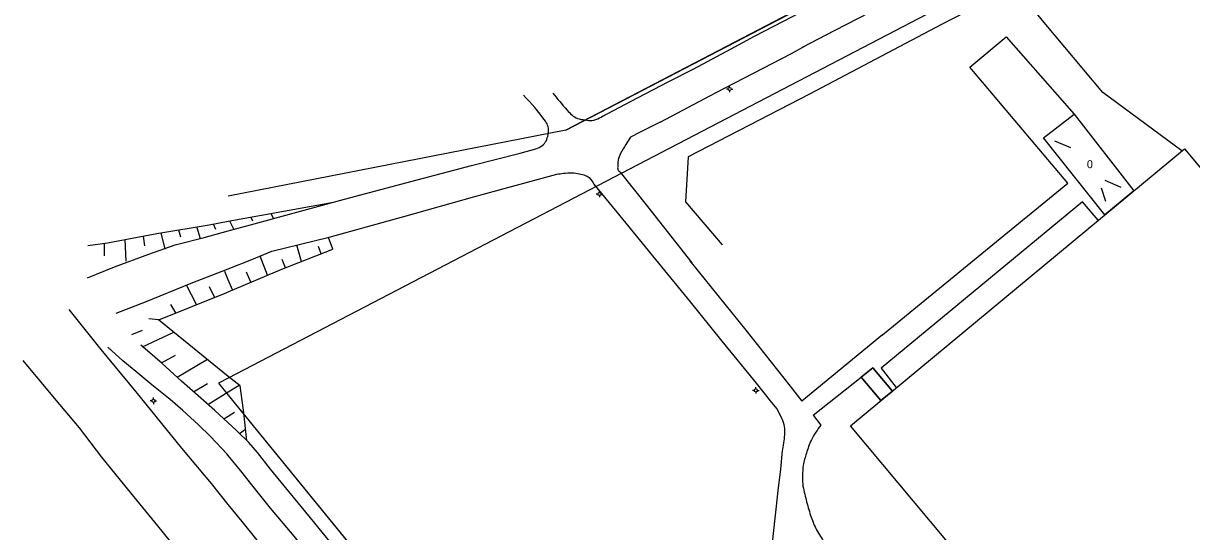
# Model space of a CAD drawing. Extents: x 1517229 to 1518128, y 6494851 to 6495271.
# Drawn here: x 1517631.6 to 1517777.6, y 6495029.8 to 6495093.3 of the extents above; entities that cross this region are included whole.
import ezdxf

# ---------------------------------------------------------------- set-up
doc = ezdxf.new("R2010")
doc.units = 0
doc.layers.add('Karta', color=7, linetype='Continuous')

msp = doc.modelspace()

# ---------------------------------------------------------------- linework, layer by layer
at = {"layer": 'Karta'}
for p, q in [((1517699.41, 6495080), (1517754.51, 6495108.72)), ((1517758.98, 6495102.02), (1517657.21, 6495048.98)), ((1517758.98, 6495102.02), (1517657.21, 6495048.98)), ((1517719.68, 6495085.13), (1517719.48, 6495085.13)), ((1517719.88, 6495085.33), (1517719.88, 6495085.53)), ((1517719.88, 6495084.93), (1517719.88, 6495084.73)), ((1517720.08, 6495085.13), (1517720.28, 6495085.13)), ((1517776.41, 6495077.41), (1517766.55, 6495084.69)), ((1517699.41, 6495080), (1517657.21, 6495071.73)), ((1517699.41, 6495080), (1517657.21, 6495071.73)), ((1517760.5, 6495078.67), (1517762.5, 6495077.81)), ((1517766.33, 6495072.76), (1517766.85, 6495071.11)), ((1517766.77, 6495073.72), (1517768.76, 6495072.85)), ((1517703.42, 6495072), (1517703.22, 6495072)), ((1517703.62, 6495072.2), (1517703.62, 6495072.4)), ((1517703.62, 6495071.8), (1517703.62, 6495071.6)), ((1517703.82, 6495072), (1517704.02, 6495072)), ((1517655.34, 6495068.26), (1517655.62, 6495067.62)), ((1517657.38, 6495068.63), (1517657.9, 6495067.58)), ((1517660.04, 6495069.11), (1517660.26, 6495068.65)), ((1517662.52, 6495069.56), (1517662.85, 6495068.93)), ((1517648.78, 6495067.16), (1517649.27, 6495065.1)), ((1517650.98, 6495067.52), (1517651.25, 6495066.67)), ((1517653.3, 6495067.83), (1517653.7, 6495066.43)), ((1517639.65, 6495065.56), (1517642.14, 6495065.9)), ((1517641.69, 6495065.84), (1517641.7, 6495064.28)), ((1517644.28, 6495066.31), (1517644.43, 6495063.59)), ((1517646.56, 6495066.74), (1517646.75, 6495065.51)), ((1517666.37, 6495063.57), (1517665.78, 6495065.61)), ((1517668.82, 6495064.53), (1517668.51, 6495065.44)), ((1517662.14, 6495061.86), (1517661.2, 6495064.24)), ((1517664.37, 6495062.79), (1517663.94, 6495063.8)), ((1517657.75, 6495060.01), (1517657.21, 6495061.28)), ((1517660.03, 6495060.97), (1517659.51, 6495062.23)), ((1517653.26, 6495058.19), (1517651.99, 6495060.61)), ((1517655.51, 6495059.09), (1517654.87, 6495060.38)), ((1517650.66, 6495057.13), (1517650.03, 6495058.2)), ((1517645.17, 6495054.45), (1517646.48, 6495054.99)), ((1517646.51, 6495052.91), (1517650.42, 6495054.73)), ((1517738.97, 6495054.38), (1517728.92, 6495046.11)), ((1517648.86, 6495050.89), (1517650.64, 6495051.85)), ((1517650.82, 6495049.1), (1517654.6, 6495051.34)), ((1517652.85, 6495047.29), (1517654.6, 6495048.3)), ((1517657.21, 6495048.98), (1517656.01, 6495048.35)), ((1517656.01, 6495048.35), (1517657.21, 6495046.87)), ((1517657.21, 6495047.26), (1517658.58, 6495048.1)), ((1517723.16, 6495047.65), (1517723.16, 6495047.85)), ((1517730.31, 6495044.37), (1517736.31, 6495049.11)), ((1517647.86, 6495046.35), (1517647.86, 6495046.55)), ((1517654.67, 6495045.71), (1517657.21, 6495047.26)), ((1517657.21, 6495046.87), (1517711.4, 6494980.36)), ((1517722.96, 6495047.45), (1517722.76, 6495047.45)), ((1517723.16, 6495047.25), (1517723.16, 6495047.05)), ((1517723.36, 6495047.45), (1517723.56, 6495047.45)), ((1517647.66, 6495046.15), (1517647.46, 6495046.15)), ((1517647.86, 6495045.95), (1517647.86, 6495045.75)), ((1517648.06, 6495046.15), (1517648.26, 6495046.15)), ((1517656.68, 6495043.89), (1517657.21, 6495044.23)), ((1517657.21, 6495044.23), (1517658.01, 6495044.75)), ((1517658.61, 6495042.08), (1517659.38, 6495042.61))]:
    msp.add_line(p, q, dxfattribs=at)
for points in [[(1517854.64, 6495192.41), (1517766.11, 6495118.41), (1517754.51, 6495108.72), (1517699.41, 6495080)], [(1517729, 6495090.35), (1517733, 6495092.46), (1517737.46, 6495094.74), (1517741.63, 6495096.92), (1517748.04, 6495100.22), (1517751.6, 6495102), (1517754.82, 6495103.85)], [(1517766.55, 6495084.69), (1517759.4, 6495093.18), (1517755.54, 6495097.93), (1517746.36, 6495093.18), (1517729.88, 6495084.48)], [(1517703.88, 6495081.67), (1517708.35, 6495084.01), (1517712.3, 6495086.08), (1517715.31, 6495087.63), (1517720.06, 6495090.17), (1517723, 6495091.73), (1517726.62, 6495093.62), (1517729.67, 6495095.18)], [(1517738.97, 6495054.38), (1517751.4, 6495064.57), (1517762.16, 6495073.35), (1517749.91, 6495087.85), (1517754.46, 6495091.66), (1517762.94, 6495081.98)], [(1517711.18, 6495081), (1517718.21, 6495084.7), (1517722.85, 6495087.09), (1517727.6, 6495089.59), (1517729.41, 6495090.57)], [(1517729.88, 6495084.48), (1517714.71, 6495076.67), (1517714.38, 6495071.03), (1517718.93, 6495065.65)], [(1517766.79, 6495069.42), (1517759.11, 6495079.02), (1517762.94, 6495081.98), (1517770.4, 6495072.42), (1517766.79, 6495069.42)], [(1517711.18, 6495081), (1517708.71, 6495079.72), (1517707.49, 6495079.1)], [(1517680.82, 6495073.76), (1517687.61, 6495075.58), (1517693.72, 6495077.13), (1517695.64, 6495077.65)], [(1517734.98, 6495043.01), (1517776.72, 6495077.67), (1517783.24, 6495069.88), (1517783.9, 6495070.37), (1517795.96, 6495055.9), (1517795.29, 6495055.3), (1517801.2, 6495048.09), (1517781.99, 6495032.2), (1517783.57, 6495030.27), (1517778.38, 6495026.04), (1517786.33, 6495016.68), (1517792.23, 6495021.58), (1517801.35, 6495010.73), (1517789.98, 6495001.11), (1517792.38, 6494998.21), (1517779.06, 6494987.16), (1517761.38, 6495008.42), (1517762.85, 6495009.67), (1517734.97, 6495043.01)], [(1517679.16, 6495069.2), (1517688.02, 6495071.69), (1517698.28, 6495074.49)], [(1517706.22, 6495074.75), (1517709.63, 6495070.44), (1517715.15, 6495063.42)], [(1517657.21, 6495067.39), (1517659.99, 6495068.16), (1517665.79, 6495069.72), (1517671.75, 6495071.38), (1517680.82, 6495073.76)], [(1517702.9, 6495073.22), (1517706.16, 6495069.28), (1517711, 6495063.34)], [(1517657.21, 6495068.6), (1517661.39, 6495069.35), (1517668.28, 6495070.6), (1517670.35, 6495070.98)], [(1517765.96, 6495068.73), (1517763.99, 6495071.03), (1517738.81, 6495050.24), (1517740.71, 6495047.83), (1517740.75, 6495047.8)], [(1517642.12, 6495065.9), (1517648.28, 6495067.07), (1517654.81, 6495068.16), (1517657.21, 6495068.6)], [(1517657.21, 6495062.66), (1517660.15, 6495063.81), (1517662.68, 6495064.84), (1517669.84, 6495066.61), (1517679.16, 6495069.2)], [(1517639.62, 6495061.54), (1517642.99, 6495062.9), (1517647.3, 6495064.48), (1517650.56, 6495065.67), (1517654.19, 6495066.55), (1517657.21, 6495067.39)], [(1517657.21, 6495059.78), (1517663.93, 6495062.61), (1517670.3, 6495065.1), (1517669.74, 6495066.58)], [(1517643.19, 6495057.12), (1517646.86, 6495058.53), (1517652.58, 6495060.85), (1517657.21, 6495062.66)], [(1517711, 6495063.34), (1517714.97, 6495058.52), (1517718.91, 6495053.6), (1517723.21, 6495048.36)], [(1517714.92, 6495063.63), (1517721.89, 6495055), (1517727.43, 6495047.97)], [(1517657.21, 6495061.28), (1517656.78, 6495062.3), (1517656.78, 6495062.23), (1517656.78, 6495062.23)], [(1517648.53, 6495056.27), (1517657.04, 6495059.71), (1517657.21, 6495059.78)], [(1517651.43, 6495040.23), (1517645.71, 6495047.29), (1517641.34, 6495052.58), (1517637.34, 6495057.56)], [(1517657.21, 6495049.21), (1517648.5, 6495056.29), (1517647.29, 6495056.4)], [(1517657.21, 6495039.32), (1517657.05, 6495039.53), (1517654.98, 6495041.7), (1517653.51, 6495043.14), (1517651.55, 6495044.92), (1517649.97, 6495046.32), (1517647.66, 6495048.15), (1517645.66, 6495049.83), (1517644.02, 6495051.16), (1517642.15, 6495052.86)], [(1517657.21, 6495043.39), (1517655.54, 6495044.96), (1517653.44, 6495046.78), (1517651.37, 6495048.6), (1517648.95, 6495050.81), (1517647.1, 6495052.39), (1517646.3, 6495053.09)], [(1517641.43, 6495039.12), (1517638.6, 6495042.77), (1517635.49, 6495046.48), (1517631.6, 6495051.17)], [(1517740.22, 6495047.36), (1517737.78, 6495050.29), (1517736.31, 6495049.11), (1517738.8, 6495046.18), (1517740.22, 6495047.36)], [(1517657.21, 6495048.98), (1517656.01, 6495048.35), (1517657.21, 6495046.87)], [(1517659.55, 6495041.18), (1517659.11, 6495044.99), (1517658.69, 6495048.01), (1517657.21, 6495049.21)], [(1517723.21, 6495048.36), (1517725.13, 6495045.95), (1517725.78, 6495045.15)], [(1517727.43, 6495047.97), (1517728.92, 6495046.11)], [(1517657.21, 6495046.87), (1517711.4, 6494980.36), (1517719.49, 6494971.68), (1517728.65, 6494964.14), (1517738.73, 6494957.86)], [(1517659.92, 6495040.82), (1517658.2, 6495042.47), (1517657.21, 6495043.39)], [(1517730.31, 6495044.37), (1517731.29, 6495043.12)], [(1517663.82, 6495035.97), (1517662.51, 6495037.6), (1517660.86, 6495039.67), (1517659.78, 6495040.94)], [(1517657.21, 6495019.59), (1517655.3, 6495021.99), (1517652.46, 6495025.53), (1517648.43, 6495030.54), (1517644.3, 6495035.55), (1517641.43, 6495039.12)], [(1517657.21, 6495033.2), (1517655.12, 6495035.8), (1517651.43, 6495040.23)], [(1517660.15, 6495035.66), (1517658.94, 6495037.18), (1517657.21, 6495039.32)], [(1517726.46, 6495039.94), (1517726.22, 6495037.6), (1517725.9, 6495034.88)], [(1517676.06, 6495016.19), (1517670.83, 6495022.55), (1517667.92, 6495026.2), (1517665.44, 6495029.21), (1517662.49, 6495032.75), (1517660.15, 6495035.66)], [(1517679.66, 6495016.62), (1517675.52, 6495021.82), (1517671.32, 6495026.83), (1517667.5, 6495031.52), (1517663.82, 6495035.97)], [(1517725.9, 6495034.88), (1517725.54, 6495031.49), (1517725.18, 6495028.4), (1517724.79, 6495025.32), (1517724.53, 6495022.91)], [(1517667.85, 6495020.03), (1517664.09, 6495024.69), (1517658.94, 6495031.07), (1517657.21, 6495033.2)]]:
    msp.add_lwpolyline(points, dxfattribs=at)
msp.add_lwpolyline([(1517738.8, 6495046.18), (1517736.31, 6495049.11), (1517737.78, 6495050.29), (1517740.22, 6495047.36)], close=True, dxfattribs=at)
for centre in [(1517719.88, 6495085.13), (1517703.62, 6495072), (1517647.86, 6495046.15), (1517723.16, 6495047.45)]:
    msp.add_circle(centre, 0.2, dxfattribs=at)
for points in [[(1517695.64, 6495077.65), (1517696.47, 6495078.07), (1517696.94, 6495078.63), (1517697.19, 6495079.41), (1517697.2, 6495080.46), (1517696.86, 6495081.1), (1517694.1, 6495084.37)], [(1517697.77, 6495084.63), (1517699.56, 6495082.5), (1517700.87, 6495081.45), (1517701.81, 6495081.27), (1517702.68, 6495081.2), (1517703.62, 6495081.52), (1517704.35, 6495081.92)], [(1517707.49, 6495079.1), (1517706.9, 6495078.19), (1517706.25, 6495077.05), (1517705.96, 6495076.22), (1517705.89, 6495075.39), (1517705.94, 6495074.98), (1517706.22, 6495074.75)], [(1517698.28, 6495074.49), (1517699.12, 6495074.59), (1517700.16, 6495074.67), (1517701.12, 6495074.51), (1517701.84, 6495074.33), (1517702.31, 6495074.07), (1517702.96, 6495073.14)], [(1517725.78, 6495045.15), (1517726.37, 6495043.98), (1517726.71, 6495042.94), (1517726.73, 6495041.91), (1517726.45, 6495039.86)], [(1517731.29, 6495043.12), (1517730.1, 6495041.28), (1517729.48, 6495039.6), (1517729.09, 6495038.1), (1517728.99, 6495036.75), (1517729.04, 6495035.4)], [(1517729.04, 6495035.47), (1517729.51, 6495033.51), (1517730.08, 6495031.59), (1517730.75, 6495030.01), (1517731.71, 6495028.4), (1517731.99, 6495027.88)]]:
    msp.add_spline(points, degree=3, dxfattribs=at)

# ---------------------------------------------------------------- texts
msp.add_text('0', height=1, dxfattribs=at).set_placement((1517764.54, 6495075.23))

doc.saveas('drawing.dxf')
